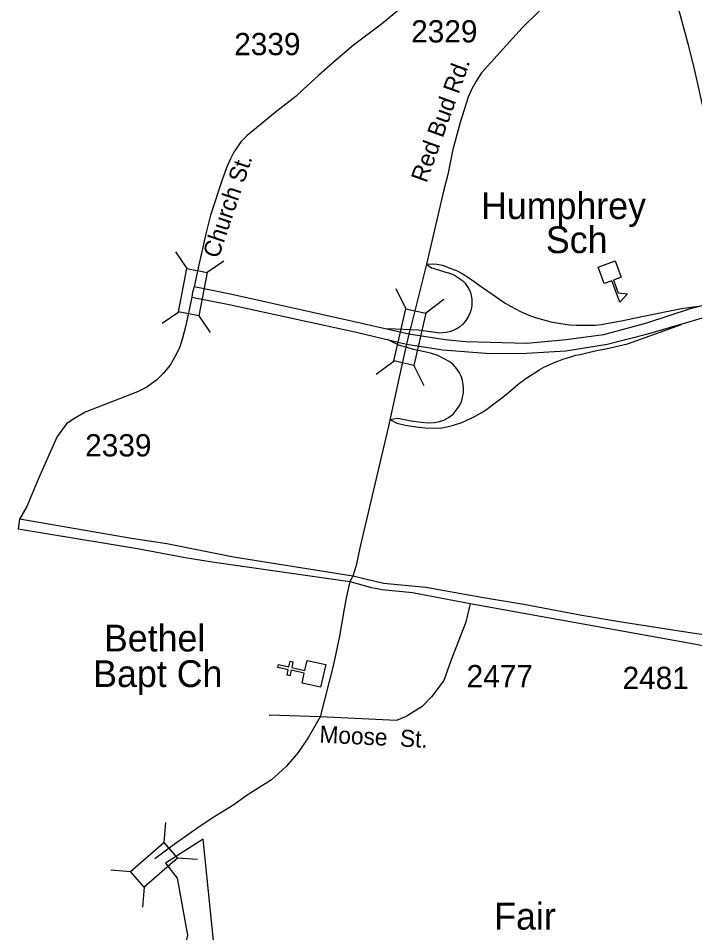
# Model space of a CAD drawing. Extents: x 1364363 to 1407445, y 538563 to 573342.
# Drawn here: x 1369476 to 1373269, y 552981 to 558110 of the extents above; entities that cross this region are included whole.
import ezdxf

# ---------------------------------------------------------------- set-up
doc = ezdxf.new("R2010")
doc.units = 0
for name, color, linetype in [('Exist Boundary Political City Limit New Hole', 7, 'Continuous'), ('Exist Cultural Church CELL', 7, 'Continuous'), ('Exist Cultural Church Label', 7, 'Continuous'), ('Exist Cultural Educational Facility High CELL', 7, 'Continuous'), ('Exist Cultural Educational Facility High Label', 7, 'Continuous'), ('Exist Cultural Recreational Fairground Label', 7, 'Continuous'), ('Exist Road Primary Interstate Divided Center Attributed', 7, 'Continuous'), ('Exist Road Primary Interstate Ramp 1 Lane Attributed', 7, 'Continuous'), ('Exist Road Primary US Divided Attributed', 7, 'Continuous'), ('Exist Road Secondary Structure Standard Bridge CELL', 7, 'Continuous'), ('Exist Road Secondary Type 51 Attributed', 7, 'Continuous'), ('Exist Road Secondary Type 51 Label', 7, 'Continuous'), ('Exist Road Secondary Type 51 Number Label', 7, 'Continuous')]:
    doc.layers.add(name, color=color, linetype=linetype)

msp = doc.modelspace()

# ---------------------------------------------------------------- linework, layer by layer
at = {"layer": 'Exist Boundary Political City Limit New Hole'}
msp.add_lwpolyline([(1370464.5, 552642.8), (1370530.2, 552576.9), (1370604.9, 552607.6), (1370512.8, 553506.8), (1370302.1, 553370.9), (1370368, 553287.5), (1370425, 552967.3), (1370389.9, 552809.4), (1370464.5, 552642.8)], dxfattribs=at)
at = {"layer": 'Exist Cultural Church CELL'}
msp.add_lwpolyline([(1371067.8, 554381), (1371080, 554436.6), (1371005.7, 554453.1), (1370998.7, 554421.9), (1370983.1, 554425.3), (1370990.1, 554456.6), (1370931.4, 554469.6), (1370934.8, 554485.3), (1370993.6, 554472.2), (1371000.5, 554503.5), (1371016.1, 554500), (1371009.2, 554468.8), (1371083.5, 554452.3), (1371096.1, 554508.5), (1371200, 554485.4), (1371171.7, 554357.9)], close=True, dxfattribs=at)
at = {"layer": 'Exist Cultural Educational Facility High CELL'}
msp.add_lwpolyline([(1372823, 556748.9), (1372857.2, 556657.2), (1372814.1, 556641.1), (1372840.3, 556570.7), (1372892.9, 556564.5), (1372850, 556517.3), (1372805.1, 556637.7), (1372762, 556621.6), (1372727.7, 556713.4)], close=True, dxfattribs=at)
at = {"layer": 'Exist Road Primary Interstate Divided Center Attributed'}
for points in [[(1371666.9, 556337.7), (1371351.4, 556408.7), (1370674.5, 556559.9), (1370461.9, 556604)], [(1370449.6, 556546), (1370659.2, 556505.1), (1371379.9, 556348.4), (1371653, 556282.3)], [(1373494.5, 556548.3), (1373361.4, 556510.6), (1373243.1, 556479.9), (1372998.8, 556399.9), (1372757.8, 556335.3), (1372548.6, 556305.7), (1372327.4, 556284.9), (1371983.2, 556294.3), (1371870.2, 556305.5), (1371666.9, 556337.7)], [(1371653, 556282.3), (1371856.4, 556250.9), (1372122.4, 556230.2), (1372326.3, 556232.5), (1372547, 556244.3), (1372777.5, 556281.7), (1373006.5, 556339.7), (1373216.8, 556401), (1373371.2, 556446), (1373503.6, 556489.2)]]:
    msp.add_lwpolyline(points, dxfattribs=at)
at = {"layer": 'Exist Road Primary Interstate Ramp 1 Lane Attributed'}
for points in [[(1371765.4, 556730.6), (1371793.5, 556710.1), (1371832.4, 556698), (1371865.5, 556688.4), (1371888.9, 556682.1), (1371905.6, 556677.1), (1371921.5, 556669.1), (1371932.8, 556662), (1371945, 556654.5), (1371958.4, 556644.6), (1371968.4, 556636.5), (1371981.3, 556623.8), (1371988.5, 556614.3), (1372001.8, 556592.9), (1372011, 556572), (1372016.5, 556553.2), (1372019.9, 556535.2), (1372020.2, 556517.6), (1372019.4, 556499.6), (1372016.9, 556485), (1372014, 556471.6), (1372008.1, 556455.7), (1372000.1, 556438.9), (1371990.2, 556421), (1371980.5, 556406.7), (1371967.1, 556392.5), (1371949.5, 556377.9), (1371928.2, 556364.5), (1371901.9, 556353.6), (1371873, 556346.9), (1371840, 556344.4), (1371719.9, 556359.9), (1371679.6, 556361.7), (1371547.2, 556367.7)], [(1371765.4, 556730.6), (1371798.5, 556732.9), (1371822.8, 556730.5), (1371855.5, 556725.4), (1371878.9, 556716.2), (1371891.3, 556710.3), (1371933.3, 556694.4), (1371965, 556678.6), (1372011, 556647.6), (1372060.4, 556613.3), (1372163.3, 556541.2), (1372189.6, 556524.1), (1372210.6, 556510.3), (1372236.5, 556494.4), (1372263.7, 556479.7), (1372291.8, 556465.1), (1372338.1, 556444.6), (1372374.1, 556432.5), (1372416.4, 556419.5), (1372462.9, 556407.8), (1372519.3, 556397.3), (1372567, 556390.6), (1372603.8, 556388.1), (1372653.1, 556388.1), (1372710.9, 556388.9), (1372747.2, 556392.7), (1372784.5, 556399), (1372858.5, 556413.2), (1372981.1, 556438.3), (1373195.7, 556481.8), (1373385.8, 556508.1)], [(1371559.3, 555860), (1371598.7, 555838.3), (1371648.2, 555828.3), (1371706.9, 555818.3), (1371757, 555812.6), (1371809.2, 555811.1), (1371850.7, 555813.3), (1371879.5, 555818.3), (1371916.7, 555827.6), (1371963.9, 555843.4), (1372007.6, 555862.7), (1372038.3, 555878.5), (1372071.4, 555896.4), (1372102.1, 555916.4), (1372143.6, 555947.9), (1372179.4, 555975.2), (1372211.6, 556000.3), (1372248.8, 556031.1), (1372279.6, 556057.6), (1372314, 556083.3), (1372338.3, 556099.8), (1372367, 556118.4), (1372396.4, 556137.7), (1372422.9, 556152.8), (1372452.9, 556166.5), (1372481.5, 556178.6), (1372507.4, 556189.4), (1372534.5, 556199.4), (1372568.1, 556209.4), (1372603.3, 556219.5), (1372627.7, 556224.4), (1372678.5, 556237.3), (1372727.1, 556248.1), (1372770.8, 556256.7), (1372891.8, 556284.3), (1373194.5, 556393)], [(1371559.3, 555860), (1371605.3, 555867.1), (1371679.6, 555852.8), (1371736.2, 555843.9), (1371774.1, 555841.8), (1371809.2, 555843.1), (1371837.9, 555848.9), (1371862.2, 555856.7), (1371888.8, 555870.4), (1371913.8, 555889.7), (1371933.9, 555913.4), (1371948.8, 555934.1), (1371961, 555959.2), (1371967.5, 555982.8), (1371972.5, 556008.6), (1371973.2, 556031.6), (1371971.7, 556055.2), (1371967.5, 556078.1), (1371959.6, 556101.8), (1371951, 556121.8), (1371938.9, 556138.3), (1371925.3, 556154), (1371912.3, 556169.8), (1371891.6, 556185.6), (1371865.1, 556200.5), (1371827.9, 556217.8), (1371788.5, 556231.4), (1371754.9, 556239.3), (1371692.6, 556252.9), (1371656.7, 556262.6), (1371613.9, 556274.4), (1371546, 556308.6)]]:
    msp.add_lwpolyline(points, dxfattribs=at)
at = {"layer": 'Exist Road Primary US Divided Attributed'}
for points in [[(1371351.9, 554980.8), (1370682.4, 555086.9), (1370309.9, 555162.5), (1370111.9, 555191.7), (1369483.8, 555300.9)], [(1369476.4, 555246), (1370144.4, 555136.5), (1370411.7, 555086), (1370563, 555061.8), (1371335.9, 554951.8)], [(1373348.3, 554648.3), (1373253.9, 554661.6), (1372858.1, 554722.9), (1372636.8, 554760.2), (1372310.4, 554822.4), (1372073.5, 554861.4), (1371761, 554918.3), (1371523.5, 554940.2), (1371351.9, 554980.8)], [(1371335.9, 554951.8), (1371448.9, 554919.9), (1371517.1, 554906.2), (1371686.3, 554888.5), (1372009.4, 554827.6)], [(1372009.4, 554827.6), (1373265.5, 554600.8), (1373342.2, 554586.8)]]:
    msp.add_lwpolyline(points, dxfattribs=at)
at = {"layer": 'Exist Road Secondary Structure Standard Bridge CELL'}
for p, q in [((1370357.4, 556799.6), (1370421.1, 556706)), ((1370628.4, 556748.1), (1370534.8, 556684.4)), ((1371593.1, 556593.6), (1371649.2, 556481)), ((1371861.9, 556531.6), (1371762.1, 556455)), ((1370376.9, 556462.1), (1370283.4, 556398.4)), ((1370488.1, 556441), (1370551.8, 556347.4)), ((1371583.6, 556187.6), (1371483.8, 556111)), ((1371693.9, 556162.1), (1371750, 556049.5)), ((1370301.3, 553600), (1370293.3, 553487.1)), ((1370482, 553391.5), (1370369.1, 553399.5)), ((1370107.3, 553323.2), (1369994.4, 553331.3)), ((1370181.4, 553237.6), (1370173.3, 553124.7))]:
    msp.add_line(p, q, dxfattribs=at)
for points in [[(1370534.8, 556684.4), (1370488.6, 556440.9), (1370374.9, 556462.5), (1370421.1, 556706)], [(1371762.1, 556455), (1371694.4, 556162), (1371581.6, 556188.1), (1371649.2, 556481)], [(1370369.1, 553399.5), (1370181.7, 553237.2), (1370105.9, 553324.7), (1370293.3, 553487.1)]]:
    msp.add_lwpolyline(points, close=True, dxfattribs=at)
at = {"layer": 'Exist Road Secondary Type 51 Attributed'}
msp.add_line((1371168.8, 554192.1), (1370883.3, 554200.9), dxfattribs=at)
for points in [[(1373657.6, 556595.2), (1373558.1, 556816.9), (1373503.2, 556988), (1373434.5, 557200), (1373394.2, 557327.6), (1373364, 557425.9), (1373326.7, 557565.7), (1373265.5, 557834.4), (1373234, 557959.1), (1373185.8, 558138.3), (1373119, 558331.9), (1372877, 558596.9)], [(1372655.5, 558398), (1372398.2, 558151.6), (1372300.9, 558057), (1372073.4, 557804.1), (1372044.4, 557757.3), (1372017.8, 557711), (1371998.7, 557667.2), (1371953.1, 557525.4), (1371913.6, 557373), (1371884.6, 557233.7), (1371860.6, 557139.9), (1371765.4, 556730.6), (1371677.1, 556379.8), (1371666.9, 556337.7)], [(1371619.5, 558164.9), (1371512.8, 558077.3), (1371355.1, 557959.7), (1371253.1, 557870.1), (1371159.4, 557788.3), (1371073.8, 557709.7), (1371034.8, 557672.1), (1370926.3, 557588.9), (1370759.8, 557451.4), (1370724.6, 557417.4), (1370705.5, 557389.1), (1370685.8, 557358.2), (1370666.6, 557321.2), (1370648.1, 557279.9), (1370621.6, 557209), (1370553.3, 557005.1), (1370527.3, 556900), (1370485.3, 556710.1), (1370461.9, 556604)], [(1370461.9, 556604), (1370453.9, 556573.2), (1370449.6, 556546)], [(1370449.6, 556546), (1370431.1, 556457.8), (1370415.6, 556386.3), (1370397.8, 556315.4), (1370383, 556266.7), (1370361.6, 556224.3), (1370327.5, 556164.9), (1370289.2, 556118), (1370252.8, 556081.7), (1370196.7, 556041.6), (1370145.5, 556013.8), (1369851.7, 555900.3), (1369781.7, 555859.6), (1369746.3, 555834.4), (1369694.7, 555763.6), (1369589.2, 555529.1), (1369523.9, 555371.8), (1369483.8, 555300.9)], [(1371666.9, 556337.7), (1371653, 556282.3)], [(1371653, 556282.3), (1371635.1, 556200.5), (1371551.9, 555823.1), (1371390.7, 555140), (1371370.7, 555041.1), (1371351.9, 554980.8)], [(1369483.8, 555300.9), (1369476.4, 555246)], [(1371351.9, 554980.8), (1371335.9, 554951.8)], [(1371335.9, 554951.8), (1371316.5, 554867.4), (1371303.5, 554798.5), (1371278.3, 554644.2), (1371242.9, 554484.7), (1371168.8, 554192.1)], [(1372009.4, 554827.6), (1371984.9, 554723.5), (1371903.8, 554512.5), (1371861.6, 554395.6), (1371793.5, 554304.7), (1371741.6, 554249.5), (1371650.7, 554194.3), (1371596.5, 554171.2), (1371168.8, 554192.1)], [(1371168.8, 554192.1), (1371103.6, 554078.5), (1371045.1, 553992.4), (1370978.5, 553914.2), (1370896.3, 553839.7), (1370753.7, 553749.9), (1370684.8, 553699.4), (1370562.7, 553623.2), (1370477.6, 553566.5), (1370349.6, 553476.4), (1370242.7, 553395.1)]]:
    msp.add_lwpolyline(points, dxfattribs=at)

# ---------------------------------------------------------------- texts
at = {"layer": 'Exist Cultural Church Label'}
for s, p in [('Bethel ', (1369956.5, 554558.6)), ('Bapt Ch', (1369896.2, 554359.3))]:
    msp.add_text(s, height=150, dxfattribs=at).set_placement(p)
at = {"layer": 'Exist Cultural Educational Facility High Label'}
for s, p in [('Humphrey', (1372070.7, 556983.7)), ('Sch', (1372434.4, 556792.7))]:
    msp.add_text(s, height=150, rotation=0, dxfattribs=at).set_placement(p)
at = {"layer": 'Exist Cultural Recreational Fairground Label'}
msp.add_text('Fair', height=150, rotation=0, dxfattribs=at).set_placement((1372144.7, 552999))
at = {"layer": 'Exist Road Secondary Type 51 Label'}
for s, rotation, p in [('Red Bud Rd.', 70.1583, (1371764.8, 557182.2)), ('Church St.', 71.3679, (1370598.6, 556758.4)), ('Moose  St.', 357.1994, (1371163.4, 554048))]:
    msp.add_text(s, height=95, rotation=rotation, dxfattribs=at).set_placement(p)
at = {"layer": 'Exist Road Secondary Type 51 Number Label'}
for s, p in [('2329', (1371679.2, 557973.9)), ('2339', (1370686.9, 557902.6)), ('2339', (1369851.3, 555652.4)), ('2477', (1371990, 554357.8)), ('2481', (1372864.4, 554347.8))]:
    msp.add_text(s, height=125, dxfattribs=at).set_placement(p)

doc.saveas('drawing.dxf')
